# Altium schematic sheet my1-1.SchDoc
size A4; SheetNumber: 0; SheetTotal: 0
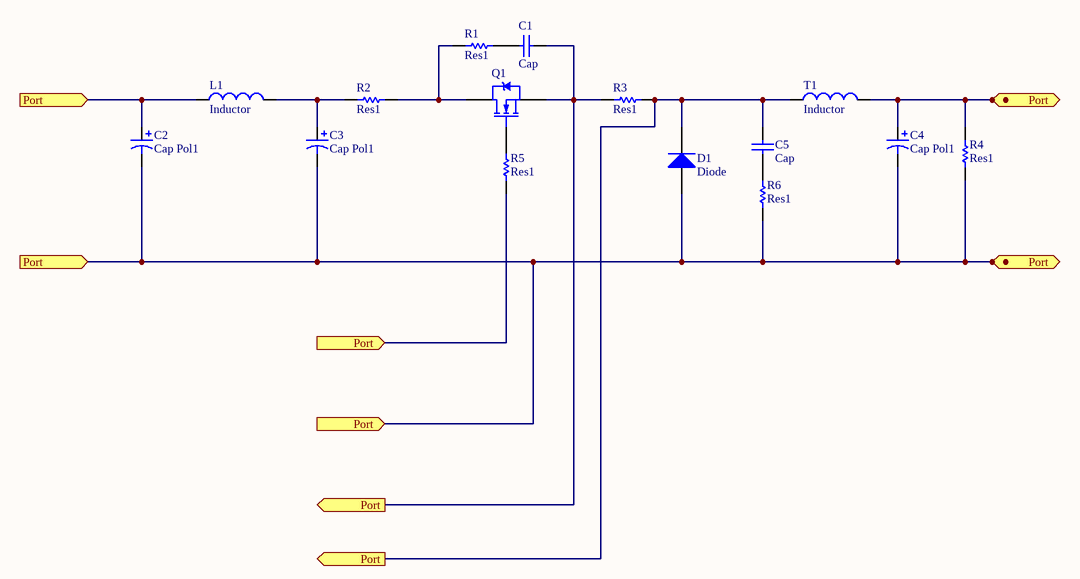
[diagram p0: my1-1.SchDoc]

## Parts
C1  Cap  [RAD-0.3]
C2  Cap Pol1  [RB7.6-15]
C3  Cap Pol1  [RB7.6-15]
C4  Cap Pol1  [RB7.6-15]
C5  Cap  [RAD-0.3]
D1  Diode  [DIO7.1-3.9x1.9]
L1  Inductor  [INDC1005-0402]
Q1  (no value)  [SFM-T3/A4.7V]
R1  Res1  [AXIAL-0.3]
R2  Res1  [AXIAL-0.3]
R3  Res1  [AXIAL-0.3]
R4  Res1  [AXIAL-0.3]
R5  Res1  [AXIAL-0.3]
R6  Res1  [AXIAL-0.3]
T1  Inductor  [INDC1005-0402]

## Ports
Port (in), Port (out)

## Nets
Port: C1.2 C2.1 C2.2 C3.2 C4.1 C4.2 C5.2 D1.1(A) D1.2(K) L1.1 Q1.3(S) R3.1 R3.2 R4.1 R4.2 R5.1 R6.1 T1.1 T1.2 ; port Port
NetC1_1: C1.1 R1.2
NetC3_1: C3.1 L1.2 R2.1
NetC5_1: C5.1 R6.2
NetQ1_2: Q1.2(D) R1.1 R2.2

Not connected (* = marked no-connect by the designer): Q1 1(G); R5 2

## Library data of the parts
C1 C5 = Cap: Capacitor
C2-C4 = Cap Pol1: Polarized Capacitor (Radial)
D1 = Diode 1N914: High Conductance Fast Diode
L1 T1 = Inductor: Code_IEC: 1005
Q1 = NMOS-2: N-Channel Power MOSFET; Note: Pin 2 is electrically connected to pin 4.
R1-R6 = Res1: Resistor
